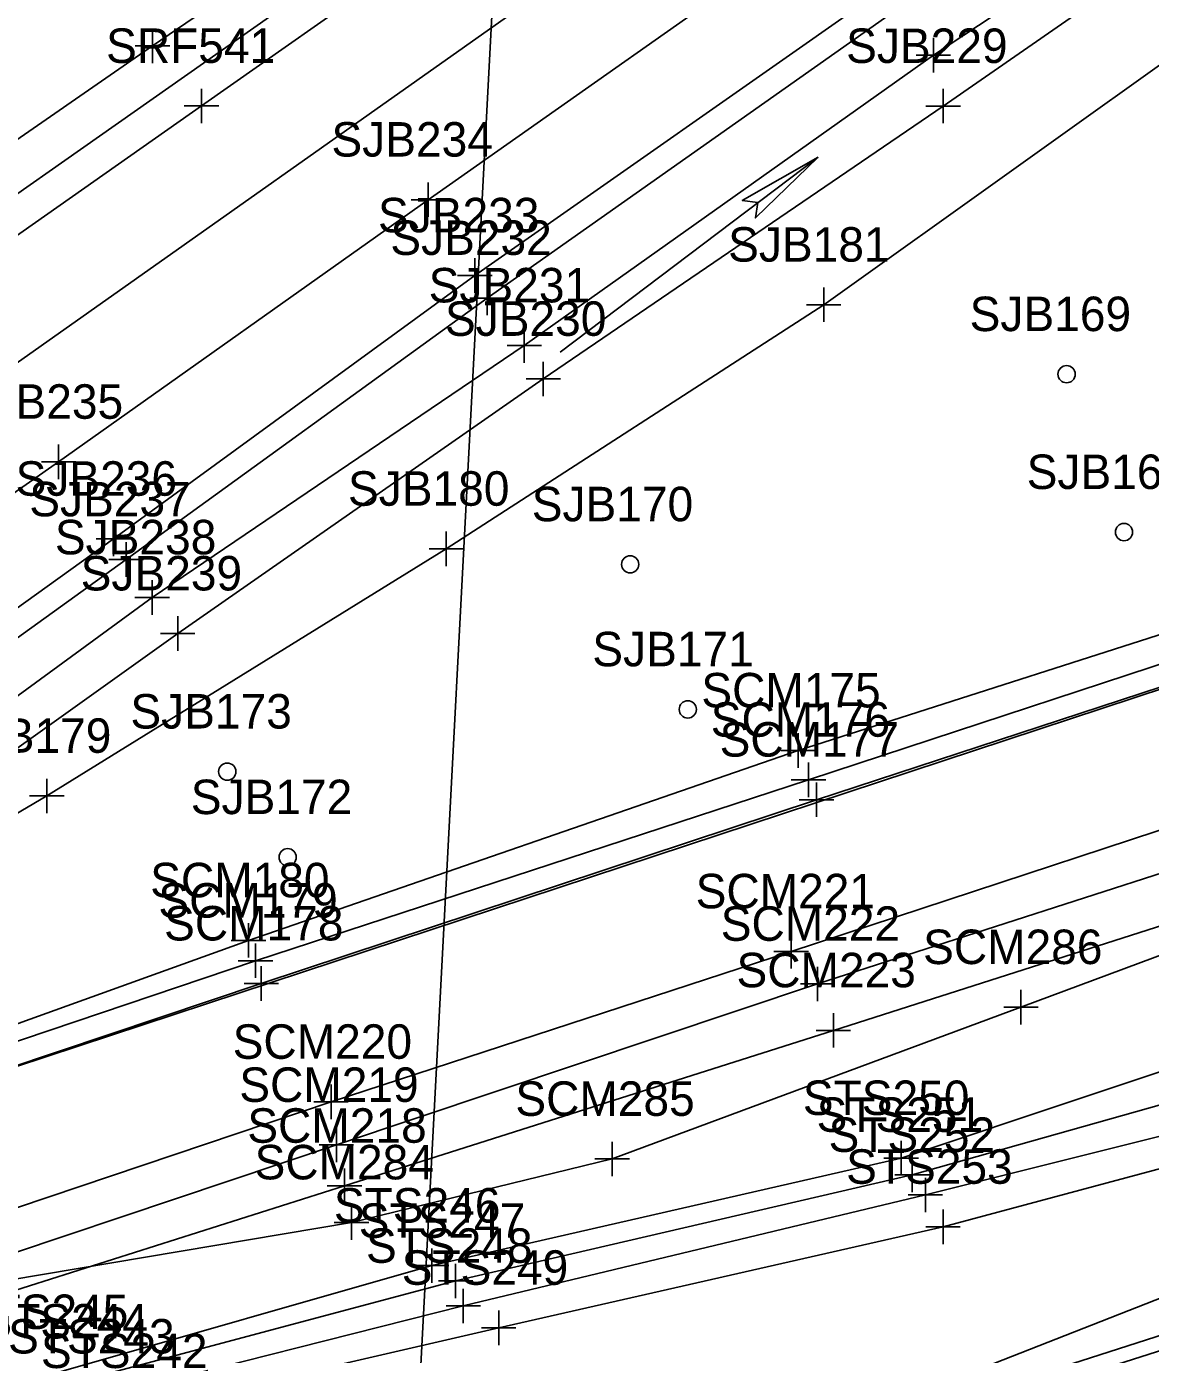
# Model space of a CAD drawing. Extents: x 941041 to 969446, y 397014 to 416764.
# Drawn here: x 951336.1 to 951466.5, y 402707.1 to 402861.1 of the extents above; entities that cross this region are included whole.
import ezdxf

# ---------------------------------------------------------------- set-up
doc = ezdxf.new("R2010")
doc.units = 0
for name, color, linetype in [('SURVEY - DRAINAGE - Area Shapes', 7, 'Continuous'), ('SURVEY - DRAINAGE - Area Shapes Text', 7, 'Continuous'), ('SURVEY - DTM - Breaklines', 7, 'Continuous'), ('SURVEY - DTM - Breaklines - Points - Locators', 7, 'Continuous'), ('SURVEY - DTM - Breaklines - Points - Numbers', 7, 'Continuous'), ('SURVEY - DTM - Spot Points - Locators', 7, 'Continuous'), ('SURVEY - DTM - Spot Points - Point Numbers', 7, 'Continuous'), ('SURVEY - DTM GRAPHICS - Boundary Line', 7, 'Continuous'), ('SURVEY - NON-TRANSPORTATION - Features', 7, 'Continuous'), ('SURVEY - PROPERTY - ROW Lines', 7, 'Continuous'), ('SURVEY - TRANSPORTATION - Features', 7, 'Continuous'), ('SURVEY - TRANSPORTATION - Features - Points - Locators', 7, 'Continuous'), ('SURVEY - TRANSPORTATION - Features - Points - Numbers', 7, 'Continuous'), ('SURVEY - TRANSPORTATION - Roads', 7, 'Continuous'), ('SURVEY - TRANSPORTATION - Roads - Points - Locators', 7, 'Continuous'), ('SURVEY - TRANSPORTATION - Roads - Points - Numbers', 7, 'Continuous'), ('SURVEY - UTILITIES - Electric (Overhead) with Text', 7, 'Continuous'), ('SURVEY - VEGETATION - Features - Points - Locators', 7, 'Continuous'), ('SURVEY - VEGETATION - Features - Points - Numbers', 7, 'Continuous'), ('SURVEY - VEGETATION - Features with Text', 7, 'Continuous')]:
    doc.layers.add(name, color=color, linetype=linetype)

msp = doc.modelspace()

# ---------------------------------------------------------------- linework, layer by layer
at = {"layer": 'SURVEY - DRAINAGE - Area Shapes'}
for points in [[(950765.73, 402528.11), (950855.07, 402487.28), (951056.09, 402625.14), (951609.08, 403015.7), (952524.78, 403657.05), (952475.83, 403724.71)], [(951056.09, 402625.14), (951316.12, 402734.28), (951765.36, 402882.47), (951798.09, 402895.65), (951826.87, 402922.65), (951854.04, 402976.32)]]:
    msp.add_lwpolyline(points, dxfattribs=at)
at = {"layer": 'SURVEY - DRAINAGE - Area Shapes Text'}
msp.add_line((951427.94, 402845.98), (951398.02, 402823.34), dxfattribs=at)
msp.add_lwpolyline([(951427.94, 402845.98), (951420.68, 402838.92), (951420.96, 402840.7), (951419.14, 402840.95)], close=True, dxfattribs=at)
msp.add_lwpolyline([(951427.94, 402845.98), (951420.68, 402838.92), (951420.96, 402840.7), (951419.14, 402840.95), (951427.94, 402845.98)], dxfattribs=at)
at = {"layer": 'SURVEY - DTM - Breaklines'}
for points in [[(951882.64, 403166.97), (951846.32, 403142.14), (951845.34, 403140.85), (951800.52, 403105.06), (951758.25, 403071.51), (951712.6, 403041.51), (951668.47, 403010.93), (951623.1, 402980.2), (951576.62, 402946.49), (951535.08, 402916.86), (951489.08, 402884.22), (951442.46, 402851.9), (951396.06, 402820.24), (951353.64, 402790.7), (951305.86, 402756.61)], [(951846.17, 403143.63), (951798.24, 403106.85), (951755.36, 403076.11), (951709.52, 403045.74), (951665.69, 403013.78), (951621.55, 402983.27), (951574.76, 402950.88), (951533.18, 402922.12), (951486.76, 402887.78), (951441.32, 402857.8), (951393.85, 402824.12), (951350.68, 402794.89), (951304.42, 402761.09), (951261.65, 402730.04), (951245.94, 402719.49)], [(951291.86, 402744.42), (951338.46, 402771.86), (951384.81, 402800.53), (951428.6, 402828.85), (951473.25, 402860.72), (951518.66, 402892.2), (951567.96, 402927.23), (951615.69, 402962.6), (951669.94, 403001.11), (951703.81, 403024.31), (951722.58, 403037.69)], [(951152.5, 402631.02), (951186.94, 402647.28), (951238.9, 402673.64), (951288.4, 402692.97), (951339.83, 402705.01), (951383.11, 402717.36), (951437.59, 402729.84), (951480.67, 402744.2), (951526.82, 402757.69), (951567.28, 402761.9), (951609.07, 402758.22), (951609.74, 402757.55)], [(951158.91, 402626.39), (951188.51, 402644.08), (951237.35, 402668.86), (951296.18, 402690.08), (951342.1, 402703.91), (951385.89, 402715.59), (951438.85, 402727.88), (951481.64, 402739.98), (951527.07, 402751.16), (951566.43, 402757.66), (951604.49, 402755.42), (951608.43, 402755.75)], [(951158.91, 402626.39), (951191.02, 402640.66), (951238.55, 402663.82), (951294.75, 402684.88), (951345.2, 402702.17), (951386.78, 402712.69), (951440.4, 402725.56), (951481.58, 402735.85), (951526.44, 402748.81), (951565.79, 402754.87), (951602.21, 402754.86), (951608.29, 402754.73)], [(951158.86, 402619.36), (951196.29, 402639.73), (951242.23, 402662.6), (951298.78, 402683.1), (951349.01, 402700.48), (951390.89, 402710.14), (951442.44, 402721.86), (951482.68, 402732.64), (951526.32, 402744.57), (951564.66, 402750.73), (951599.2, 402751.35), (951608.12, 402751.5)]]:
    msp.add_lwpolyline(points, dxfattribs=at)
at = {"layer": 'SURVEY - DTM - Breaklines - Points - Locators'}
for p, q in [((951441.32, 402859.8), (951441.32, 402855.8)), ((951443.32, 402857.8), (951439.32, 402857.8)), ((951442.46, 402853.9), (951442.46, 402849.9)), ((951444.46, 402851.9), (951440.46, 402851.9)), ((951428.6, 402830.85), (951428.6, 402826.85)), ((951430.6, 402828.85), (951426.6, 402828.85)), ((951393.85, 402826.12), (951393.85, 402822.12)), ((951395.85, 402824.12), (951391.85, 402824.12)), ((951396.06, 402822.24), (951396.06, 402818.24)), ((951398.06, 402820.24), (951394.06, 402820.24)), ((951384.81, 402802.53), (951384.81, 402798.53)), ((951386.81, 402800.53), (951382.81, 402800.53)), ((951350.68, 402796.89), (951350.68, 402792.89)), ((951352.68, 402794.89), (951348.68, 402794.89)), ((951353.64, 402792.7), (951353.64, 402788.7)), ((951355.64, 402790.7), (951351.64, 402790.7)), ((951338.46, 402773.86), (951338.46, 402769.86)), ((951340.46, 402771.86), (951336.46, 402771.86)), ((951437.59, 402731.84), (951437.59, 402727.84)), ((951439.59, 402729.84), (951435.59, 402729.84)), ((951438.85, 402729.88), (951438.85, 402725.88)), ((951440.85, 402727.88), (951436.85, 402727.88)), ((951440.4, 402727.56), (951440.4, 402723.56)), ((951442.4, 402725.56), (951438.4, 402725.56)), ((951442.44, 402723.86), (951442.44, 402719.86)), ((951444.44, 402721.86), (951440.44, 402721.86)), ((951383.11, 402719.36), (951383.11, 402715.36)), ((951385.11, 402717.36), (951381.11, 402717.36)), ((951385.89, 402717.59), (951385.89, 402713.59)), ((951387.89, 402715.59), (951383.89, 402715.59)), ((951386.78, 402714.69), (951386.78, 402710.69)), ((951388.78, 402712.69), (951384.78, 402712.69)), ((951390.89, 402712.14), (951390.89, 402708.14)), ((951392.89, 402710.14), (951388.89, 402710.14))]:
    msp.add_line(p, q, dxfattribs=at)
at = {"layer": 'SURVEY - DTM - Spot Points - Locators'}
for centre in [(951456.78, 402820.79), (951463.44, 402802.47), (951406.14, 402798.73), (951412.83, 402781.9), (951359.39, 402774.68), (951366.4, 402764.75)]:
    msp.add_circle(centre, 1, dxfattribs=at)
at = {"layer": 'SURVEY - DTM GRAPHICS - Boundary Line'}
msp.add_lwpolyline([(951119.87, 402541.66), (951195.66, 402594.37), (951229.64, 402619.17), (951268.93, 402645.14), (951305.23, 402657.24), (951391.81, 402684.89), (951506.96, 402721.92), (951601.15, 402751.07), (951598.54, 402730.16), (951605.18, 402712.87), (951604.23, 402665.8), (951604.97, 402580.51), (951602.48, 402563.89)], dxfattribs=at)
at = {"layer": 'SURVEY - NON-TRANSPORTATION - Features'}
msp.add_lwpolyline([(951119.87, 402541.66), (951195.66, 402594.37), (951229.64, 402619.17), (951268.93, 402645.14), (951305.23, 402657.24), (951391.81, 402684.89), (951506.96, 402721.92), (951601.15, 402751.07)], dxfattribs=at)
at = {"layer": 'SURVEY - PROPERTY - ROW Lines'}
msp.add_line((951270.4, 402644.92), (951816.57, 402818.19), dxfattribs=at)
at = {"layer": 'SURVEY - TRANSPORTATION - Features'}
for points in [[(951856.72, 403212.68), (951764.5, 403147.89), (951717.58, 403116.6), (951672.86, 403085.82), (951622.89, 403050.6), (951589.61, 403026.67), (951541.47, 402992.46), (951493.88, 402958.88), (951445.62, 402924.24), (951399.07, 402891.81), (951350.72, 402858.88), (951303.21, 402826.01), (951256.16, 402792.29), (951210.71, 402760.72), (951159.21, 402724.85), (951109.63, 402690.18), (951062.08, 402656.92), (951014.84, 402623.15), (950965.73, 402588.73), (950917.42, 402555.24)], [(951845.47, 403150.79), (951794.85, 403112.74), (951750.76, 403081.68), (951706.8, 403050.62), (951661.08, 403019.6), (951617.49, 402989.41), (951570.55, 402956.66), (951529.62, 402928.23), (951481.56, 402894.72), (951437.37, 402863.29), (951389.55, 402829.63), (951347.66, 402799.3), (951299.97, 402764.93), (951259.62, 402733.33), (951238.85, 402716.85), (951240.37, 402714.07), (951266.38, 402722.33)], [(951846.56, 403091.78), (951845.62, 403090.54), (951844.19, 403053.45), (951841.06, 403003.88), (951840.1, 402982.66), (951838.45, 402972.77), (951834.7, 402957.88), (951827.04, 402938.23), (951820.46, 402926.15), (951809.1, 402913.09), (951795.85, 402902.54), (951764.02, 402888.59), (951699.7, 402866.96), (951667.03, 402856.79), (951633.83, 402847.29), (951594.02, 402835.22), (951574.16, 402829.05), (951546.44, 402816.84), (951480.21, 402794.6), (951425.64, 402777.13), (951361.86, 402755.1), (951314.06, 402737.89), (951266.38, 402722.33)], [(951277.47, 402695.38), (951316.92, 402708.83), (951373, 402726.62), (951429.72, 402744.66), (951491.99, 402764.58), (951552.79, 402784.52), (951610.6, 402803.9), (951656.17, 402821.45), (951718.78, 402842.22), (951766.16, 402854.36), (951780.18, 402854.15), (951793.68, 402852.43), (951804.96, 402846.44), (951811.85, 402837.56), (951816.74, 402824)]]:
    msp.add_lwpolyline(points, dxfattribs=at)
at = {"layer": 'SURVEY - TRANSPORTATION - Features - Points - Locators'}
for p, q in [((951350.72, 402860.88), (951350.72, 402856.88)), ((951352.72, 402858.88), (951348.72, 402858.88)), ((951389.55, 402831.63), (951389.55, 402827.63)), ((951391.55, 402829.63), (951387.55, 402829.63)), ((951347.66, 402801.3), (951347.66, 402797.3)), ((951349.66, 402799.3), (951345.66, 402799.3)), ((951425.64, 402779.13), (951425.64, 402775.13)), ((951427.64, 402777.13), (951423.64, 402777.13)), ((951361.86, 402757.1), (951361.86, 402753.1)), ((951363.86, 402755.1), (951359.86, 402755.1)), ((951429.72, 402746.66), (951429.72, 402742.66)), ((951431.72, 402744.66), (951427.72, 402744.66)), ((951373, 402728.62), (951373, 402724.62)), ((951375, 402726.62), (951371, 402726.62))]:
    msp.add_line(p, q, dxfattribs=at)
at = {"layer": 'SURVEY - TRANSPORTATION - Roads'}
for points in [[(951858.06, 403203.77), (951808.39, 403168.94), (951765.12, 403138.61), (951722.92, 403109), (951677.22, 403076.95), (951628.72, 403042.91), (951593.38, 403018.09), (951546.63, 402985.29), (951497.78, 402951.07), (951450.21, 402917.78), (951402.73, 402884.45), (951356.41, 402851.91), (951307.81, 402817.83), (951261.24, 402785.24), (951215.15, 402752.96), (951165.07, 402717.74), (951114.38, 402682.19), (951068.41, 402650.05), (951019.3, 402615.59), (950970.87, 402581.82), (950921.09, 402547.35)], [(951799.91, 403167.92), (951765.7, 403143.84), (951722.98, 403113.79), (951681.01, 403084.4), (951636.93, 403053.52), (951591.07, 403021.41), (951548.97, 402991.96), (951506.9, 402962.52), (951461.04, 402930.25), (951416.05, 402898.59), (951370.52, 402866.66), (951326.63, 402835.85), (951281.83, 402804.38), (951236.39, 402772.61), (951191.53, 402741.41), (951141.44, 402706.16), (951090.99, 402670.89), (951041.99, 402636.44), (950997.25, 402605.16), (950947.61, 402570.96)], [(951846.26, 403165.91), (951785.95, 403123.91), (951742.66, 403093.3), (951698.88, 403062.61), (951653.78, 403030.96), (951609.85, 403000.51), (951563.27, 402967.88), (951522.4, 402938.86), (951473.6, 402904.83), (951429.78, 402874.17), (951382.72, 402841.04), (951339.82, 402810.62), (951292.16, 402777.26), (951248.3, 402746.75), (951245.27, 402744.51), (951200.71, 402713.1), (951156.14, 402681.85), (951111.63, 402650.98), (951070.06, 402621.38)], [(951848.45, 403157.23), (951792.22, 403116.66), (951747.92, 403084.66), (951704.82, 403054.15), (951659.86, 403022.58), (951616, 402991.97), (951569.24, 402959.23), (951528.22, 402930.38), (951479.58, 402896.46), (951435.74, 402865.6), (951388.12, 402832.25), (951346.18, 402801.69), (951298.05, 402767.12), (951257.18, 402736.22), (951253.47, 402733.27), (951213.31, 402701.79), (951214.38, 402699.39), (951243.59, 402710.94), (951265.42, 402718.75)], [(951839.36, 402956.2), (951831.8, 402938.12), (951824.82, 402924.58), (951812.18, 402910.34), (951797.13, 402897.96), (951784.98, 402891.23), (951765.13, 402883.6), (951713.83, 402867.13), (951667.99, 402853.17), (951635.64, 402842.16), (951596.86, 402828.93), (951575.85, 402822.32), (951547.75, 402813.45), (951504.97, 402799.57), (951480.95, 402791.51), (951426.84, 402773.73), (951362.66, 402752.74), (951314.74, 402736.56), (951267.51, 402719.52), (951265.42, 402718.75)], [(951838.82, 402949.53), (951834.35, 402936.96), (951826.87, 402922.65), (951814.29, 402908), (951798.09, 402895.65), (951785.66, 402889.57), (951765.36, 402882.47), (951714.37, 402865.61), (951668.43, 402850.51), (951636.44, 402839.9), (951597.52, 402827.1), (951576.73, 402820.37), (951548.16, 402811.05), (951505.55, 402797.08), (951481.9, 402789.14), (951427.76, 402771.42), (951363.34, 402750.09), (951316.12, 402734.28), (951266.91, 402717.03)], [(951273.58, 402702.54), (951313.07, 402716.73), (951371.43, 402736.36), (951424.82, 402753.82), (951488.51, 402774.76), (951548.11, 402794.58), (951608.67, 402814.56), (951652.69, 402828.65), (951716.09, 402849.74), (951762.86, 402865.2), (951780.27, 402870.18), (951814.27, 402865.67), (951829.77, 402849.1), (951832.66, 402840.42)], [(951275.49, 402697.96), (951315.76, 402712.5), (951372.05, 402731.36), (951427.89, 402750.05), (951489.84, 402770.02), (951550.95, 402790.11), (951608.9, 402809), (951655.28, 402824.8), (951717.33, 402844.53), (951764.59, 402860.4), (951780, 402860.61), (951793.78, 402858.95), (951808.21, 402851.92), (951815.2, 402839.55), (951821.02, 402827.46)]]:
    msp.add_lwpolyline(points, dxfattribs=at)
at = {"layer": 'SURVEY - TRANSPORTATION - Roads - Points - Locators'}
for p, q in [((951356.41, 402853.91), (951356.41, 402849.91)), ((951358.41, 402851.91), (951354.41, 402851.91)), ((951382.72, 402843.04), (951382.72, 402839.04)), ((951384.72, 402841.04), (951380.72, 402841.04)), ((951388.12, 402834.25), (951388.12, 402830.25)), ((951390.12, 402832.25), (951386.12, 402832.25)), ((951339.82, 402812.62), (951339.82, 402808.62)), ((951341.82, 402810.62), (951337.82, 402810.62)), ((951346.18, 402803.69), (951346.18, 402799.69)), ((951348.18, 402801.69), (951344.18, 402801.69)), ((951426.84, 402775.73), (951426.84, 402771.73)), ((951428.84, 402773.73), (951424.84, 402773.73)), ((951427.76, 402773.42), (951427.76, 402769.42)), ((951429.76, 402771.42), (951425.76, 402771.42)), ((951424.82, 402755.82), (951424.82, 402751.82)), ((951362.66, 402754.74), (951362.66, 402750.74)), ((951426.82, 402753.82), (951422.82, 402753.82)), ((951364.66, 402752.74), (951360.66, 402752.74)), ((951363.34, 402752.09), (951363.34, 402748.09)), ((951427.89, 402752.05), (951427.89, 402748.05)), ((951365.34, 402750.09), (951361.34, 402750.09)), ((951429.89, 402750.05), (951425.89, 402750.05)), ((951371.43, 402738.36), (951371.43, 402734.36)), ((951373.43, 402736.36), (951369.43, 402736.36)), ((951372.05, 402733.36), (951372.05, 402729.36)), ((951374.05, 402731.36), (951370.05, 402731.36))]:
    msp.add_line(p, q, dxfattribs=at)
at = {"layer": 'SURVEY - UTILITIES - Electric (Overhead) with Text'}
msp.add_line((951403.15, 403110.87), (951380.24, 402675.06), dxfattribs=at)
at = {"layer": 'SURVEY - VEGETATION - Features - Points - Locators'}
for p, q in [((951451.48, 402749.35), (951451.48, 402745.35)), ((951453.48, 402747.35), (951449.48, 402747.35)), ((951404.06, 402731.74), (951404.06, 402727.74)), ((951406.06, 402729.74), (951402.06, 402729.74)), ((951373.8, 402724.37), (951373.8, 402720.37)), ((951375.8, 402722.37), (951371.8, 402722.37))]:
    msp.add_line(p, q, dxfattribs=at)
at = {"layer": 'SURVEY - VEGETATION - Features with Text'}
msp.add_lwpolyline([(951228.2, 402619.62), (951212.51, 402647.2), (951322.04, 402713.67), (951373.8, 402722.37), (951404.06, 402729.74), (951451.48, 402747.35), (951523.17, 402774.05), (951568.22, 402788.21), (951587.47, 402760.6), (951228.2, 402619.62)], dxfattribs=at)

# ---------------------------------------------------------------- texts
at = {"layer": 'SURVEY - DTM - Breaklines - Points - Numbers'}
for s, p in [('SJB229', (951431.2, 402856.9)), ('SJB181', (951417.51, 402833.85)), ('SJB231', (951382.76, 402829.12)), ('SJB230', (951384.65, 402825.24)), ('SJB180', (951373.4, 402805.53)), ('SJB238', (951339.39, 402799.89)), ('SJB239', (951342.38, 402795.7)), ('SJB179', (951327.21, 402776.86)), ('STS250', (951426.18, 402734.84)), ('STS251', (951427.77, 402732.88)), ('STS252', (951429.16, 402730.56)), ('STS253', (951431.2, 402726.86)), ('STS246', (951371.76, 402722.36)), ('STS247', (951374.65, 402720.59)), ('STS248', (951375.49, 402717.69)), ('STS249', (951379.63, 402715.14)), ('STS245', (951328.59, 402710.01)), ('STS244', (951330.86, 402708.91)), ('STS243', (951333.96, 402707.17)), ('STS242', (951337.77, 402705.48))]:
    msp.add_text(s, height=4, dxfattribs=at).set_placement(p)
at = {"layer": 'SURVEY - DTM - Spot Points - Point Numbers'}
for s, p in [('SJB169', (951445.53, 402825.79)), ('SJB168', (951452.15, 402807.47)), ('SJB170', (951394.72, 402803.73)), ('SJB171', (951401.75, 402786.9)), ('SJB173', (951348.15, 402779.68)), ('SJB172', (951355.16, 402769.75))]:
    msp.add_text(s, height=4, dxfattribs=at).set_placement(p)
at = {"layer": 'SURVEY - TRANSPORTATION - Features - Points - Numbers'}
for s, p in [('SJB232', (951378.31, 402834.63)), ('SJB237', (951336.42, 402804.3)), ('SCM175', (951414.4, 402782.13)), ('SCM180', (951350.45, 402760.1)), ('SCM223', (951418.48, 402749.66)), ('SCM218', (951361.72, 402731.62))]:
    msp.add_text(s, height=4, dxfattribs=at).set_placement(p)
at = {"layer": 'SURVEY - TRANSPORTATION - Roads - Points - Numbers'}
for s, p in [('SRF541', (951345.33, 402856.91)), ('SJB234', (951371.48, 402846.04)), ('SJB233', (951376.88, 402837.25)), ('SJB235', (951328.58, 402815.62)), ('SJB236', (951334.83, 402806.69)), ('SCM176', (951415.49, 402778.73)), ('SCM177', (951416.52, 402776.42)), ('SCM221', (951413.74, 402758.82)), ('SCM179', (951351.4, 402757.74)), ('SCM178', (951352.06, 402755.09)), ('SCM222', (951416.65, 402755.05)), ('SCM220', (951360.02, 402741.36)), ('SCM219', (951360.79, 402736.36))]:
    msp.add_text(s, height=4, dxfattribs=at).set_placement(p)
at = {"layer": 'SURVEY - VEGETATION - Features - Points - Numbers'}
for s, p in [('SCM286', (951440.13, 402752.35)), ('SCM285', (951392.82, 402734.74)), ('SCM284', (951362.56, 402727.37))]:
    msp.add_text(s, height=4, dxfattribs=at).set_placement(p)

doc.saveas('drawing.dxf')
